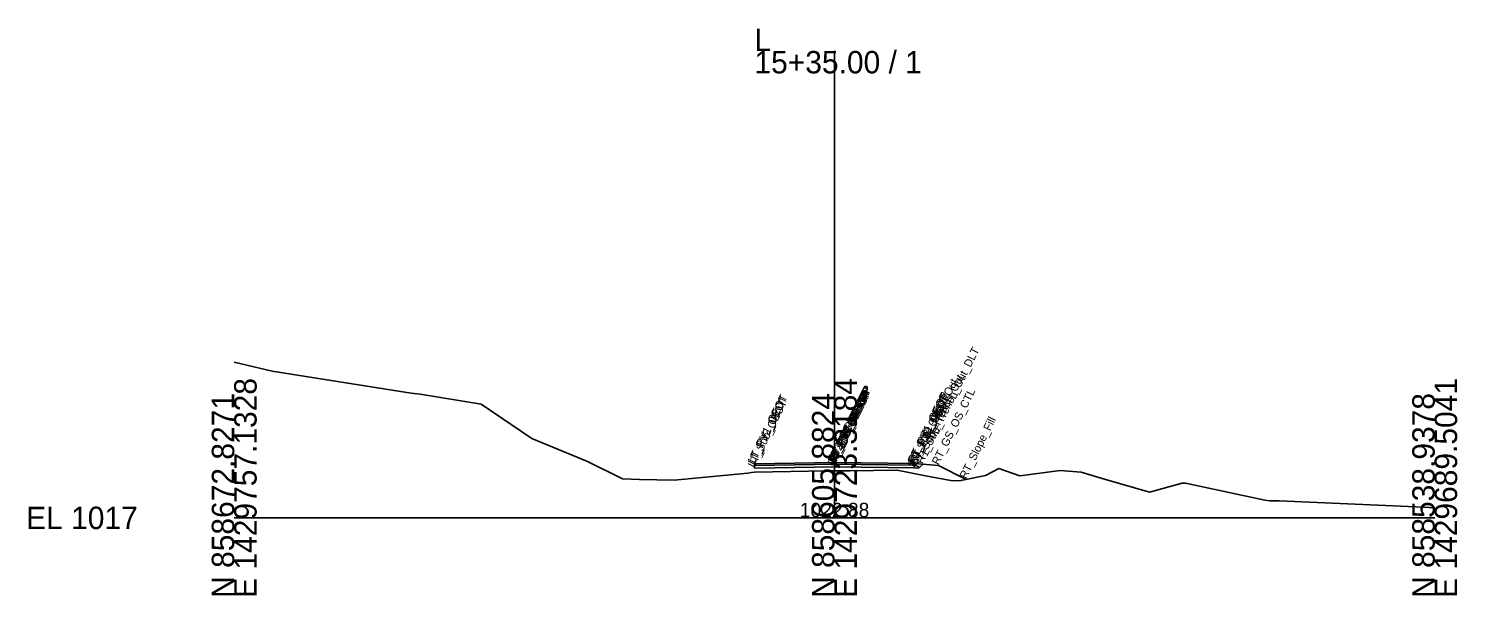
# Model space of a CAD drawing. Extents: x -26 to 2303, y -10 to 19558.
# Drawn here: x 2124.3 to 2302.8, y 4990.3 to 5061.2 of the extents above; entities that cross this region are included whole.
import ezdxf

# ---------------------------------------------------------------- set-up
doc = ezdxf.new("R2010")
doc.units = 0
for name, color, linetype in [('Default', 7, 'Continuous'), ('Exist Cross Section Cell', 7, 'Continuous'), ('Exist XS Center Line Elevation Label', 7, 'Continuous'), ('Exist XS Ground Line', 7, 'Continuous'), ('Prop CMT Pvmt Course 1', 7, 'Continuous'), ('Prop CMT Pvmt Course 2', 7, 'Continuous'), ('Prop CMT Pvmt Surface', 7, 'Continuous'), ('Prop CMT Pvmt Surface Shoulder', 7, 'Continuous'), ('Prop CMT Shld Paved Course 1', 7, 'Continuous'), ('Prop CMT Shld Paved Course 2', 7, 'Continuous'), ('Prop CMT Slope Grass', 7, 'Continuous'), ('Prop CMT Subgrade Earthwork', 7, 'Continuous'), ('Prop XS Dump Level', 7, 'Continuous')]:
    doc.layers.add(name, color=color, linetype=linetype)

msp = doc.modelspace()

# ---------------------------------------------------------------- linework, layer by layer
at = {"layer": 'Exist Cross Section Cell'}
for p, q in [((2225, 5000), (2225, 5058.36)), ((2150, 5000), (2225, 5000)), ((2225, 5000), (2300, 5000))]:
    msp.add_line(p, q, dxfattribs=at)
at = {"layer": 'Exist XS Ground Line'}
msp.add_lwpolyline([(2150, 5019.45), (2154.73, 5018.35), (2172.13, 5015.59), (2172.86, 5015.49), (2173.25, 5015.47), (2180.86, 5014.21), (2187.19, 5009.93), (2194.13, 5007.05), (2198.53, 5004.87), (2200.66, 5004.81), (2204.98, 5004.7), (2214.16, 5005.6), (2214.62, 5005.67), (2215.02, 5005.72), (2223.99, 5005.87), (2225, 5005.88), (2226.91, 5005.9), (2232.83, 5005.96), (2236.39, 5005.27), (2239.76, 5004.63), (2240.81, 5004.67), (2243.87, 5005.29), (2245.53, 5006.16), (2248.18, 5005.26), (2253.21, 5005.92), (2255.84, 5005.71), (2258.44, 5004.92), (2264.38, 5003.23), (2268.46, 5004.35), (2268.87, 5004.33), (2278.78, 5002.21), (2279.38, 5002.14), (2280.56, 5002.14), (2298.59, 5001.36), (2300, 5001.27)], dxfattribs=at)
at = {"layer": 'Prop CMT Pvmt Course 1'}
for points in [[(2225, 5006.94), (2215, 5006.74)], [(2215, 5006.74), (2215, 5006.53)], [(2215, 5006.53), (2225, 5006.73)], [(2225, 5006.73), (2225, 5006.94)], [(2225, 5006.94), (2235, 5006.78)], [(2225, 5006.73), (2225, 5006.94)], [(2235, 5006.57), (2225, 5006.73)], [(2235, 5006.78), (2235, 5006.57)]]:
    msp.add_lwpolyline(points, dxfattribs=at)
msp.add_lwpolyline([(2225, 5006.73), (2225, 5006.81), (2225, 5006.81), (2225, 5006.73)], close=True, dxfattribs=at)
msp.add_lwpolyline([(2225, 5006.73), (2225, 5006.81), (2225, 5006.81), (2225, 5006.73)], close=True, dxfattribs=at)
at = {"layer": 'Prop CMT Pvmt Course 2'}
for points in [[(2225, 5006.73), (2215, 5006.53)], [(2215, 5006.53), (2215, 5006.2)], [(2215, 5006.2), (2225, 5006.4)], [(2225, 5006.4), (2225, 5006.73)], [(2225, 5006.4), (2225, 5006.73)], [(2225, 5006.73), (2235, 5006.57)], [(2235, 5006.24), (2225, 5006.4)], [(2235, 5006.57), (2235, 5006.24)]]:
    msp.add_lwpolyline(points, dxfattribs=at)
at = {"layer": 'Prop CMT Pvmt Surface'}
for points in [[(2225, 5006.94), (2215, 5006.74)], [(2225, 5006.94), (2235, 5006.78)]]:
    msp.add_lwpolyline(points, dxfattribs=at)
at = {"layer": 'Prop CMT Pvmt Surface Shoulder'}
msp.add_lwpolyline([(2235, 5006.78), (2235, 5006.78)], dxfattribs=at)
at = {"layer": 'Prop CMT Shld Paved Course 1'}
for points in [[(2235, 5006.78), (2235, 5006.78)], [(2235, 5006.78), (2235.21, 5006.56)], [(2235, 5006.57), (2235, 5006.78)], [(2235.21, 5006.56), (2235, 5006.57)]]:
    msp.add_lwpolyline(points, dxfattribs=at)
at = {"layer": 'Prop CMT Shld Paved Course 2'}
for points in [[(2235, 5006.57), (2235.21, 5006.56)], [(2235, 5006.24), (2235, 5006.57)], [(2235.55, 5006.22), (2235, 5006.24)], [(2235.21, 5006.56), (2235.21, 5006.56)], [(2235.21, 5006.56), (2235.55, 5006.22)]]:
    msp.add_lwpolyline(points, dxfattribs=at)
at = {"layer": 'Prop CMT Slope Grass'}
msp.add_lwpolyline([(2235, 5006.78), (2238, 5006.54), (2241.47, 5004.8)], dxfattribs=at)
at = {"layer": 'Prop CMT Subgrade Earthwork'}
for points in [[(2225, 5006.4), (2215, 5006.2)], [(2225, 5006.4), (2235, 5006.24)], [(2235, 5006.24), (2235.55, 5006.22)], [(2235.55, 5006.22), (2236.02, 5006.69)]]:
    msp.add_lwpolyline(points, dxfattribs=at)

# ---------------------------------------------------------------- texts
at = {"layer": 'Default'}
msp.add_text('-', height=0.0001, dxfattribs=at).set_placement((2150, 5000))
at = {"layer": 'Exist Cross Section Cell'}
for s, p in [('L', (2215, 5058.36)), ('15+35.00 / 1', (2215, 5055.56)), ('EL 1017', (2124, 4998.6))]:
    msp.add_text(s, height=2.8, dxfattribs=at).set_placement(p)
for s, p in [('E 1429757.1328', (2152.8, 4990)), ('E 1429723.3184', (2227.8, 4990)), ('E 1429689.5041', (2302.8, 4990)), ('N 858672.8271', (2150, 4990)), ('N 858605.8824', (2225, 4990)), ('N 858538.9378', (2300, 4990))]:
    msp.add_text(s, height=2.8, rotation=90, dxfattribs=at).set_placement(p)
at = {"layer": 'Exist XS Center Line Elevation Label'}
msp.add_text('1022.88', height=1.8, dxfattribs=at).set_placement((2220.66, 5000.08))
at = {"layer": 'Prop XS Dump Level'}
for s, p in [('RT_Sub_Trench_Out_DLT', (2236.02, 5006.69)), ('RT_PS2_Shelf_Out', (2235.21, 5006.56)), ('RT_Sub_Trench_Out', (2235.55, 5006.22)), ('LT_PV1_OEOT', (2215, 5006.74)), ('LT_PV2_OEOT', (2215, 5006.53)), ('RT_PV1_OEEOP', (2225, 5006.81)), ('RT_PV2_OEEOP', (2225, 5006.73)), ('LT_PV1_OEEOP', (2225, 5006.81)), ('LT_PV2_OEEOP', (2225, 5006.73)), ('RT_Sub_OEEOP', (2225, 5006.4)), ('RT_PV1_IEEOP', (2225, 5006.81)), ('RT_PV2_IEEOP', (2225, 5006.73)), ('LT_Sub_OEEOP', (2225, 5006.4)), ('LT_PV1_IEEOP', (2225, 5006.81)), ('LT_PV2_IEEOP', (2225, 5006.73)), ('RT_PV1_OEOT', (2235, 5006.78)), ('RT_PS1_OEOP', (2235, 5006.78)), ('RT_PV2_OEOT', (2235, 5006.57)), ('RT_Sub_OEOT', (2235, 5006.24)), ('RT_PS2_OEOP', (2235.21, 5006.56)), ('RT_GS_OS_CTL', (2238, 5006.54)), ('LT_Sub_OEOT', (2215, 5006.2)), ('PV1_PGL', (2225, 5006.94)), ('PV2_PGL', (2225, 5006.73)), ('RT_Slope_Fill', (2241.47, 5004.8))]:
    msp.add_text(s, height=1, rotation=63.5833, dxfattribs=at).set_placement(p)

doc.saveas('drawing.dxf')
